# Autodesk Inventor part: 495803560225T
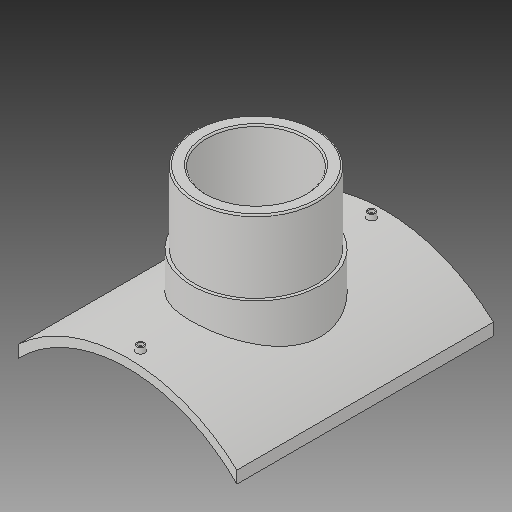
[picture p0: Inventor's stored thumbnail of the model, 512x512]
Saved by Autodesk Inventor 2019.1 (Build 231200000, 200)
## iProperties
Created: 2017-10
Part Number: 495803560225T
Material: Generic
Description: PLASSON BRANCH SADDLE  560x225
Document SubType Name: Modeling
Designer: KIM
Mass: 2754.05 g
Surface Area: 3037.44 cm^2
Volume: 2754.05 cm^3
Density: 1 g/cm^3
Appearance: Default
Author: KIM
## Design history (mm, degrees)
derived "495803.ipt"
feature "Solid1::495803.ipt"
tag "TaggingFeature1"
body "Solid1"
other parameters: "d1" = 16, "d4" = 0, "d12" = 305.6, "d13" = 14, "d14" = 211.5, "d16" = 5 deg, "d18" = 4, "d19" = 14, "d20" = 0, "d21" = 3, "d22" = 0, "d23" = 485, "d24" = 236.25, "d25" = 16, "d28" = 0, "d29" = 9.6, "d31" = 0, "d32" = 94.5, "d33" = 0, "d34" = 5.6, "d36" = 225, "d37" = 132.3, "d38" = 0, "d39" = 2.8, "d_1" = 225, "H_" = 189, "x_" = 16, "D_" = 16
